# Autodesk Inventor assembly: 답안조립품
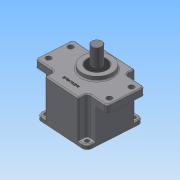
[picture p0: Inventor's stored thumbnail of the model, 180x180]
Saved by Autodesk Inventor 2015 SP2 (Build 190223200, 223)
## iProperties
Created: 2015-06
Part Number: 답안조립품
Document SubType Name: Assembly
Designer: AMC
Author: AMC
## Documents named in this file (11)
- C:\Users\AMC\Desktop\450620V1017\답안조립품.iam
- C:\Users\AMC\Desktop\450620V1017\1번본체.ipt
- C:\Users\AMC\Desktop\450620V1017\2번커버.ipt
- C:\Users\AMC\Desktop\450620V1017\베어링 608.ipt
- 베어링 608.ipt
- C:\Users\AMC\Desktop\450620V1017\메인축.ipt
- C:\Users\AMC\Desktop\450620V1017\서브축.ipt
- C:\Users\AMC\Desktop\450620V1017\베어링 6003.ipt
- 베어링 6003.ipt
- C:\Users\AMC\Desktop\450620V1017\오일실 8x22x7.ipt
- C:\Users\AMC\Desktop\450620V1017\오일실 17x32x8.ipt
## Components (2 placed, 2 different names)
1. 1번본체:1
2. 2번커버:1
